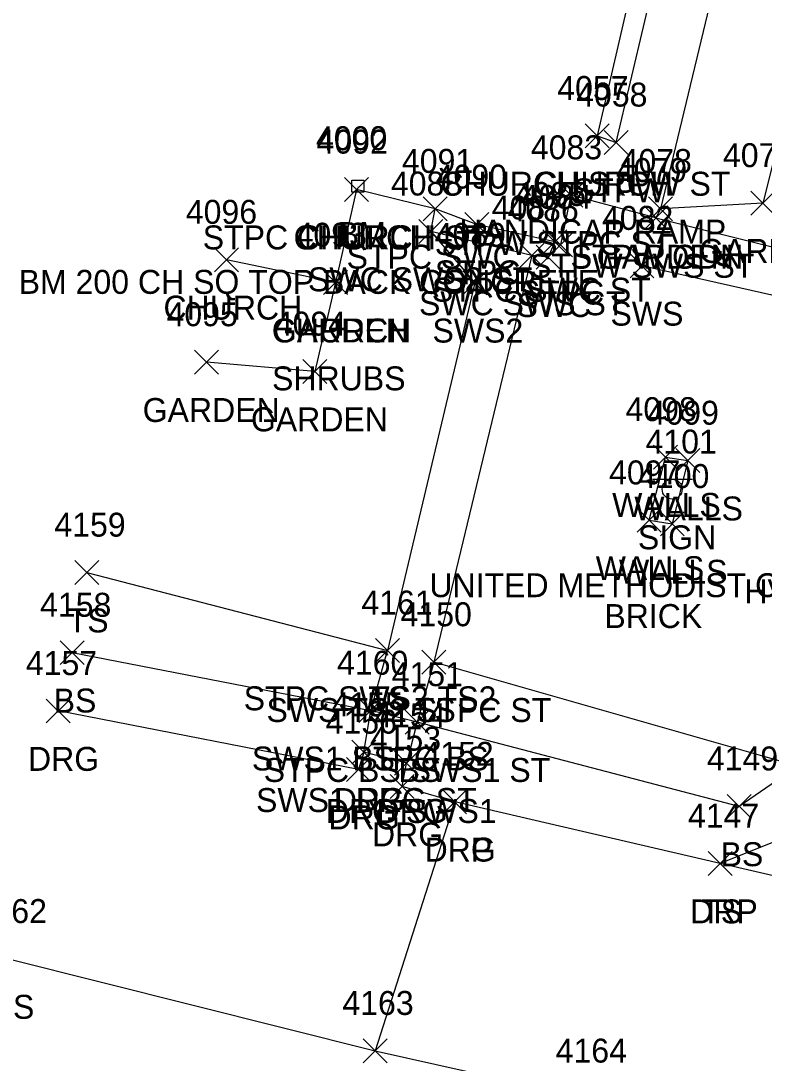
# Model space of a CAD drawing. Extents: x 1443912 to 1445411, y 621446 to 623693.
# Drawn here: x 1444916.3 to 1444978.4, y 623518.7 to 623605.8 of the extents above; entities that cross this region are included whole.
import ezdxf

# ---------------------------------------------------------------- set-up
doc = ezdxf.new("R2010")
doc.units = 0
for name, color, linetype in [('C_A', 7, 'Continuous'), ('C_C', 7, 'Continuous'), ('C_I', 7, 'Continuous'), ('CPBM', 7, 'Continuous'), ('L_A', 7, 'Continuous'), ('L_C', 7, 'Continuous'), ('L_I', 7, 'Continuous'), ('L_TIC', 7, 'Continuous'), ('LAPB', 7, 'Continuous'), ('LBC', 7, 'Continuous'), ('LBF', 7, 'Continuous'), ('LELB', 7, 'Continuous'), ('LWS', 7, 'Continuous'), ('R_A', 7, 'Continuous'), ('R_I', 7, 'Continuous'), ('R_TIC', 7, 'Continuous'), ('RDG', 7, 'Continuous'), ('RDP', 7, 'Continuous'), ('RSW', 7, 'Continuous'), ('S_A', 7, 'Continuous'), ('S_C', 7, 'Continuous'), ('S_I', 7, 'Continuous'), ('SSGN', 7, 'Continuous')]:
    doc.layers.add(name, color=color, linetype=linetype)

msp = doc.modelspace()

# ---------------------------------------------------------------- linework, layer by layer
at = {"layer": 'CPBM'}
for p, q in [((1444943.962, 623591.516), (1444943.962, 623592.516)), ((1444943.962, 623592.516), (1444944.962, 623592.516)), ((1444944.962, 623592.516), (1444944.962, 623591.516)), ((1444944.962, 623591.516), (1444943.962, 623591.516)), ((1444944.465, 623592.017), (1444944.465, 623592.017)), ((1444944.465, 623592.017), (1444944.465, 623592.017))]:
    msp.add_line(p, q, dxfattribs=at)
at = {"layer": 'L_TIC'}
for points in [[(1444963.441, 623595.216), (1444965.441, 623597.216)], [(1444965.441, 623595.216), (1444963.441, 623597.216)], [(1444963.441, 623595.216), (1444965.441, 623597.216)], [(1444965.441, 623595.216), (1444963.441, 623597.216)], [(1444965.022, 623594.665), (1444967.022, 623596.665)], [(1444967.022, 623594.665), (1444965.022, 623596.665)], [(1444943.347, 623590.734), (1444945.347, 623592.734)], [(1444945.347, 623590.734), (1444943.347, 623592.734)], [(1444943.347, 623590.734), (1444945.347, 623592.734)], [(1444945.347, 623590.734), (1444943.347, 623592.734)], [(1444961.24, 623590.26), (1444963.24, 623592.26)], [(1444963.24, 623590.26), (1444961.24, 623592.26)], [(1444961.24, 623590.26), (1444963.24, 623592.26)], [(1444963.24, 623590.26), (1444961.24, 623592.26)], [(1444977.278, 623589.604), (1444979.278, 623591.604)], [(1444979.278, 623589.604), (1444977.278, 623591.604)], [(1444949.909, 623589.126), (1444951.909, 623591.126)], [(1444951.909, 623589.126), (1444949.909, 623591.126)], [(1444968.731, 623589.117), (1444970.731, 623591.117)], [(1444970.731, 623589.117), (1444968.731, 623591.117)], [(1444968.731, 623589.117), (1444970.731, 623591.117)], [(1444970.731, 623589.117), (1444968.731, 623591.117)], [(1444953.38, 623587.81), (1444955.38, 623589.81)], [(1444955.38, 623587.81), (1444953.38, 623589.81)], [(1444968.347, 623588.362), (1444970.347, 623590.362)], [(1444970.347, 623588.362), (1444968.347, 623590.362)], [(1444959.893, 623586.361), (1444961.893, 623588.361)], [(1444961.893, 623586.361), (1444959.893, 623588.361)], [(1444960.374, 623586.124), (1444962.374, 623588.124)], [(1444962.374, 623586.124), (1444960.374, 623588.124)], [(1444932.488, 623584.869), (1444934.488, 623586.869)], [(1444934.488, 623584.869), (1444932.488, 623586.869)], [(1444941.6, 623582.957), (1444943.6, 623584.957)], [(1444943.6, 623582.957), (1444941.6, 623584.957)], [(1444941.6, 623582.957), (1444943.6, 623584.957)], [(1444943.6, 623582.957), (1444941.6, 623584.957)], [(1444930.822, 623576.314), (1444932.822, 623578.314)], [(1444932.822, 623576.314), (1444930.822, 623578.314)], [(1444939.858, 623575.53), (1444941.858, 623577.53)], [(1444941.858, 623575.53), (1444939.858, 623577.53)], [(1444969.143, 623568.383), (1444971.143, 623570.383)], [(1444971.143, 623568.383), (1444969.143, 623570.383)], [(1444970.995, 623568.087), (1444972.995, 623570.087)], [(1444972.995, 623568.087), (1444970.995, 623570.087)], [(1444967.768, 623563.099), (1444969.768, 623565.099)], [(1444969.768, 623563.099), (1444967.768, 623565.099)], [(1444967.768, 623563.099), (1444969.768, 623565.099)], [(1444969.768, 623563.099), (1444967.768, 623565.099)], [(1444969.71, 623562.797), (1444971.71, 623564.797)], [(1444971.71, 623562.797), (1444969.71, 623564.797)], [(1444969.71, 623562.797), (1444971.71, 623564.797)], [(1444971.71, 623562.797), (1444969.71, 623564.797)], [(1444920.821, 623558.733), (1444922.821, 623560.733)], [(1444922.821, 623558.733), (1444920.821, 623560.733)], [(1444919.617, 623552.041), (1444921.617, 623554.041)], [(1444921.617, 623552.041), (1444919.617, 623554.041)], [(1444945.925, 623552.226), (1444947.925, 623554.226)], [(1444947.925, 623552.226), (1444945.925, 623554.226)], [(1444945.925, 623552.226), (1444947.925, 623554.226)], [(1444947.925, 623552.226), (1444945.925, 623554.226)], [(1444949.804, 623551.247), (1444951.804, 623553.247)], [(1444951.804, 623551.247), (1444949.804, 623553.247)], [(1444949.804, 623551.247), (1444951.804, 623553.247)], [(1444951.804, 623551.247), (1444949.804, 623553.247)], [(1444944.548, 623547.198), (1444946.548, 623549.198)], [(1444946.548, 623547.198), (1444944.548, 623549.198)], [(1444944.548, 623547.198), (1444946.548, 623549.198)], [(1444946.548, 623547.198), (1444944.548, 623549.198)], [(1444948.406, 623546.241), (1444950.406, 623548.241)], [(1444950.406, 623546.241), (1444948.406, 623548.241)], [(1444948.406, 623546.241), (1444950.406, 623548.241)], [(1444950.406, 623546.241), (1444948.406, 623548.241)], [(1444975.298, 623539.202), (1444977.298, 623541.202)], [(1444977.298, 623539.202), (1444975.298, 623541.202)], [(1444973.709, 623534.424), (1444975.709, 623536.424)], [(1444975.709, 623534.424), (1444973.709, 623536.424)], [(1444944.908, 623518.775), (1444946.908, 623520.775)], [(1444946.908, 623518.775), (1444944.908, 623520.775)]]:
    msp.add_lwpolyline(points, dxfattribs=at)
at = {"layer": 'LAPB'}
for points in [[(1444978.069, 623624.879), (1444985.504, 623619.429), (1444978.278, 623590.604), (1444969.731, 623590.117)], [(1444942.6, 623583.957), (1444940.858, 623576.53), (1444931.822, 623577.314)]]:
    msp.add_lwpolyline(points, dxfattribs=at)
at = {"layer": 'LBC'}
for points in [[(1444972.255, 623630.072), (1444964.441, 623596.216)], [(1444944.347, 623591.734), (1444942.6, 623583.957), (1444933.488, 623585.869)]]:
    msp.add_lwpolyline(points, dxfattribs=at)
at = {"layer": 'LBF'}
for points in [[(1444964.441, 623596.216), (1444966.022, 623595.665), (1444973.192, 623626.107), (1444978.069, 623624.879), (1444969.731, 623590.117), (1444969.347, 623589.362), (1444962.24, 623591.26)], [(1444962.24, 623591.26), (1444961.374, 623587.124), (1444960.893, 623587.361), (1444954.38, 623588.81), (1444950.909, 623590.126), (1444944.347, 623591.734)], [(1444950.804, 623552.247), (1444949.406, 623547.241), (1444945.548, 623548.198), (1444946.925, 623553.226)]]:
    msp.add_lwpolyline(points, dxfattribs=at)
at = {"layer": 'LELB'}
for points in [[(1444990.989, 623580.204), (1444981.2, 623543.556), (1444976.298, 623540.202), (1444949.406, 623547.241)], [(1444921.821, 623559.733), (1444946.925, 623553.226)], [(1444920.617, 623553.041), (1444945.548, 623548.198)], [(1444981.2, 623543.556), (1444950.804, 623552.247)], [(1444986.637, 623540.215), (1444974.709, 623535.424)], [(1444915.29, 623527.453), (1444945.908, 623519.775)]]:
    msp.add_lwpolyline(points, dxfattribs=at)
at = {"layer": 'LWS'}
for points in [[(1444968.768, 623564.099), (1444970.143, 623569.383), (1444971.995, 623569.087), (1444970.71, 623563.797)], [(1444968.768, 623564.099), (1444970.71, 623563.797)]]:
    msp.add_lwpolyline(points, dxfattribs=at)
at = {"layer": 'R_TIC'}
for points in [[(1444949.909, 623589.126), (1444951.909, 623591.126)], [(1444951.909, 623589.126), (1444949.909, 623591.126)], [(1444968.347, 623588.362), (1444970.347, 623590.362)], [(1444970.347, 623588.362), (1444968.347, 623590.362)], [(1444949.555, 623587.232), (1444951.555, 623589.232)], [(1444951.555, 623587.232), (1444949.555, 623589.232)], [(1444949.555, 623587.232), (1444951.555, 623589.232)], [(1444951.555, 623587.232), (1444949.555, 623589.232)], [(1444959.893, 623586.361), (1444961.893, 623588.361)], [(1444961.893, 623586.361), (1444959.893, 623588.361)], [(1444957.972, 623585.229), (1444959.972, 623587.229)], [(1444959.972, 623585.229), (1444957.972, 623587.229)], [(1444957.972, 623585.229), (1444959.972, 623587.229)], [(1444959.972, 623585.229), (1444957.972, 623587.229)], [(1444959.339, 623585.082), (1444961.339, 623587.082)], [(1444961.339, 623585.082), (1444959.339, 623587.082)], [(1444967.178, 623584.362), (1444969.178, 623586.362)], [(1444969.178, 623584.362), (1444967.178, 623586.362)], [(1444953.216, 623582.948), (1444955.216, 623584.948)], [(1444955.216, 623582.948), (1444953.216, 623584.948)], [(1444945.925, 623552.226), (1444947.925, 623554.226)], [(1444947.925, 623552.226), (1444945.925, 623554.226)], [(1444949.804, 623551.247), (1444951.804, 623553.247)], [(1444951.804, 623551.247), (1444949.804, 623553.247)], [(1444918.431, 623547.167), (1444920.431, 623549.167)], [(1444920.431, 623547.167), (1444918.431, 623549.167)], [(1444944.548, 623547.198), (1444946.548, 623549.198)], [(1444946.548, 623547.198), (1444944.548, 623549.198)], [(1444948.406, 623546.241), (1444950.406, 623548.241)], [(1444950.406, 623546.241), (1444948.406, 623548.241)], [(1444943.956, 623543.728), (1444945.956, 623545.728)], [(1444945.956, 623543.728), (1444943.956, 623545.728)], [(1444943.956, 623543.728), (1444945.956, 623545.728)], [(1444945.956, 623543.728), (1444943.956, 623545.728)], [(1444947.522, 623542.813), (1444949.522, 623544.813)], [(1444949.522, 623542.813), (1444947.522, 623544.813)], [(1444947.522, 623542.813), (1444949.522, 623544.813)], [(1444949.522, 623542.813), (1444947.522, 623544.813)], [(1444943.516, 623542.275), (1444945.516, 623544.275)], [(1444945.516, 623542.275), (1444943.516, 623544.275)], [(1444947.148, 623540.856), (1444949.148, 623542.856)], [(1444949.148, 623540.856), (1444947.148, 623542.856)], [(1444951.54, 623539.586), (1444953.54, 623541.586)], [(1444953.54, 623539.586), (1444951.54, 623541.586)], [(1444951.54, 623539.586), (1444953.54, 623541.586)], [(1444953.54, 623539.586), (1444951.54, 623541.586)], [(1444973.709, 623534.424), (1444975.709, 623536.424)], [(1444975.709, 623534.424), (1444973.709, 623536.424)], [(1444944.908, 623518.775), (1444946.908, 623520.775)], [(1444946.908, 623518.775), (1444944.908, 623520.775)]]:
    msp.add_lwpolyline(points, dxfattribs=at)
at = {"layer": 'RDG'}
for points in [[(1444944.956, 623544.728), (1444944.516, 623543.275), (1444919.431, 623548.167)], [(1444952.54, 623540.586), (1444948.148, 623541.856), (1444948.522, 623543.813)]]:
    msp.add_lwpolyline(points, dxfattribs=at)
at = {"layer": 'RDP'}
msp.add_lwpolyline([(1444989.647, 623532.72), (1444984.082, 623533.247), (1444974.709, 623535.424), (1444952.54, 623540.586), (1444945.908, 623519.775), (1444963.712, 623515.793), (1444978.902, 623513.727), (1444983.263, 623509.219)], dxfattribs=at)
at = {"layer": 'RSW'}
for points in [[(1444960.893, 623587.361), (1444960.339, 623586.082), (1444958.972, 623586.229), (1444950.555, 623588.232), (1444950.909, 623590.126)], [(1444969.347, 623589.362), (1444991.751, 623583.781), (1444990.989, 623580.204), (1444968.178, 623585.362)], [(1444950.555, 623588.232), (1444954.216, 623583.948), (1444946.925, 623553.226)], [(1444958.972, 623586.229), (1444950.804, 623552.247)], [(1444949.406, 623547.241), (1444948.522, 623543.813), (1444944.956, 623544.728), (1444945.548, 623548.198)]]:
    msp.add_lwpolyline(points, dxfattribs=at)
at = {"layer": 'SSGN'}
for p, q in [((1444969.053, 623567.531), (1444972.386, 623567.531)), ((1444970.699, 623566.698), (1444970.699, 623566.698))]:
    msp.add_line(p, q, dxfattribs=at)
msp.add_circle((1444970.699, 623566.698), 0.833, dxfattribs=at)

# ---------------------------------------------------------------- texts
at = {"layer": 'C_A'}
for s, p in [('BM', (1444942.78, 623587.017)), ('HVCTRL', (1444976.73, 623557.157))]:
    msp.add_text(s, height=2, dxfattribs=at).set_placement(p)
at = {"layer": 'C_C'}
msp.add_text('BM 200 CH SQ TOP BACK CONCRETE', height=2, dxfattribs=at).set_placement((1444916.135, 623583.017))
at = {"layer": 'C_I'}
msp.add_text('4000', height=2, dxfattribs=at).set_placement((1444940.961, 623595.017))
at = {"layer": 'L_A'}
for s, p in [('CHURCH STPW ST', (1444951.347, 623591.216)), ('CHURCH', (1444959.181, 623591.216)), ('STPW', (1444962.415, 623590.665)), ('STPC CHURCH ST', (1444931.505, 623586.734)), ('CHURCH', (1444939.088, 623586.734)), ('STPW STPC ST', (1444950.878, 623586.26)), ('STPW STPC ST', (1444950.878, 623586.26)), ('STPC SWC', (1444943.516, 623585.126)), ('STPW GDN', (1444962.212, 623585.117)), ('GARDEN', (1444964.401, 623585.117)), ('GARDEN', (1444972.947, 623585.604)), ('STPW SWS ST', (1444958.835, 623584.362)), ('STPC', (1444950.892, 623583.81)), ('STPC SWC ST', (1444950.633, 623582.361)), ('STPC', (1444957.886, 623582.124)), ('CHURCH', (1444928.228, 623580.869)), ('GARDEN', (1444937.27, 623578.957)), ('CHURCH', (1444937.341, 623578.957)), ('GARDEN', (1444926.491, 623572.314)), ('GARDEN', (1444935.528, 623571.53)), ('WALLS', (1444965.686, 623564.383)), ('WALLS', (1444967.539, 623564.087)), ('WALLS', (1444964.312, 623559.099)), ('WALLS', (1444964.312, 623559.099)), ('WALLS', (1444966.253, 623558.797)), ('WALLS', (1444966.253, 623558.797)), ('TS', (1444920.231, 623554.733)), ('BS', (1444919.058, 623548.041)), ('STPC SWS2 TS2', (1444934.925, 623548.226)), ('TS', (1444945.334, 623548.226)), ('SWS TS2 STPC ST', (1444936.828, 623547.247)), ('TS', (1444949.214, 623547.247)), ('SWS1 STPC BS', (1444935.612, 623543.198)), ('BS', (1444943.989, 623543.198)), ('STPC BS SWS1 ST', (1444936.595, 623542.241)), ('BS', (1444947.847, 623542.241)), ('BS', (1444974.739, 623535.202)), ('TS', (1444973.119, 623530.424)), ('CS', (1444913.731, 623522.453))]:
    msp.add_text(s, height=2, dxfattribs=at).set_placement(p)
at = {"layer": 'L_C'}
for s, p in [('HANDICAP RAMP', (1444952.922, 623587.216)), ('SHRUBS', (1444937.293, 623574.957)), ('BRICK', (1444965.036, 623555.099)), ('BRICK', (1444965.036, 623555.099))]:
    msp.add_text(s, height=2, dxfattribs=at).set_placement(p)
at = {"layer": 'L_I'}
for s, p in [('4057', (1444961.103, 623599.216)), ('4057', (1444961.103, 623599.216)), ('4058', (1444962.683, 623598.665)), ('4092', (1444941.009, 623594.734)), ('4092', (1444941.009, 623594.734)), ('4083', (1444958.901, 623594.26)), ('4083', (1444958.901, 623594.26)), ('4091', (1444948.138, 623593.126)), ('4078', (1444966.393, 623593.117)), ('4078', (1444966.393, 623593.117)), ('4077', (1444974.939, 623593.604)), ('4079', (1444966.001, 623592.362)), ('4090', (1444950.955, 623591.81)), ('4085', (1444957.554, 623590.361)), ('4084', (1444958.035, 623590.124)), ('4096', (1444930.094, 623588.869)), ('4093', (1444939.262, 623586.957)), ('4093', (1444939.262, 623586.957)), ('4095', (1444928.483, 623580.314)), ('4094', (1444937.52, 623579.53)), ('4098', (1444966.804, 623572.383)), ('4099', (1444968.649, 623572.087)), ('4097', (1444965.43, 623567.099)), ('4097', (1444965.43, 623567.099)), ('4100', (1444967.852, 623566.797)), ('4100', (1444967.852, 623566.797)), ('4159', (1444919.121, 623562.733)), ('4158', (1444917.924, 623556.041)), ('4161', (1444944.752, 623556.226)), ('4161', (1444944.752, 623556.226)), ('4150', (1444948.025, 623555.247)), ('4150', (1444948.025, 623555.247)), ('4160', (1444942.722, 623551.198)), ('4160', (1444942.722, 623551.198)), ('4151', (1444947.28, 623550.241)), ('4151', (1444947.28, 623550.241)), ('4149', (1444973.597, 623543.202)), ('4147', (1444972.017, 623538.424)), ('4162', (1444912.55, 623530.453)), ('4163', (1444943.168, 623522.775))]:
    msp.add_text(s, height=2, dxfattribs=at).set_placement(p)
at = {"layer": 'R_A'}
for s, p in [('STPC SWC', (1444943.516, 623585.126)), ('STPW SWS ST', (1444958.835, 623584.362)), ('SWC SWS2 ST', (1444940.295, 623583.232)), ('SWC SWS2 ST', (1444940.295, 623583.232)), ('STPC SWC ST', (1444950.633, 623582.361)), ('SWC SWS ST', (1444949.562, 623581.229)), ('SWC SWS ST', (1444949.562, 623581.229)), ('SWC', (1444957.701, 623581.082)), ('SWS', (1444965.548, 623580.362)), ('SWS2', (1444950.688, 623578.948)), ('STPC SWS2 TS2', (1444934.925, 623548.226)), ('SWS TS2 STPC ST', (1444936.828, 623547.247)), ('DRG', (1444916.919, 623543.167)), ('SWS1 STPC BS', (1444935.612, 623543.198)), ('STPC BS SWS1 ST', (1444936.595, 623542.241)), ('SWS1 DRG ST', (1444935.956, 623539.728)), ('DRG', (1444942.444, 623539.728)), ('DRG SWS1', (1444941.781, 623538.813)), ('DRG', (1444942.005, 623538.275)), ('DRG', (1444946.01, 623538.813)), ('DRG', (1444945.636, 623536.856)), ('DRG', (1444950.028, 623535.586)), ('DRP', (1444950.028, 623535.586)), ('DRP', (1444972.198, 623530.424))]:
    msp.add_text(s, height=2, dxfattribs=at).set_placement(p)
at = {"layer": 'R_I'}
for s, p in [('4091', (1444948.138, 623593.126)), ('4079', (1444966.001, 623592.362)), ('4088', (1444947.216, 623591.232)), ('4088', (1444947.216, 623591.232)), ('4085', (1444957.554, 623590.361)), ('4087', (1444955.633, 623589.229)), ('4087', (1444955.633, 623589.229)), ('4086', (1444956.945, 623589.082)), ('4082', (1444964.839, 623588.362)), ('4089', (1444950.87, 623586.948)), ('4161', (1444944.752, 623556.226)), ('4150', (1444948.025, 623555.247)), ('4157', (1444916.738, 623551.167)), ('4160', (1444942.722, 623551.198)), ('4151', (1444947.28, 623550.241)), ('4155', (1444942.263, 623547.728)), ('4155', (1444942.263, 623547.728)), ('4154', (1444945.829, 623546.813)), ('4154', (1444945.829, 623546.813)), ('4156', (1444941.769, 623546.275)), ('4153', (1444945.455, 623544.856)), ('4152', (1444949.847, 623543.586)), ('4152', (1444949.847, 623543.586)), ('4147', (1444972.017, 623538.424)), ('4163', (1444943.168, 623522.775)), ('4164', (1444960.972, 623518.793)), ('4164', (1444960.972, 623518.793))]:
    msp.add_text(s, height=2, dxfattribs=at).set_placement(p)
at = {"layer": 'S_A'}
msp.add_text('SIGN', height=2, dxfattribs=at).set_placement((1444967.837, 623561.677))
at = {"layer": 'S_C'}
msp.add_text('UNITED METHODIST CHURCH', height=2, dxfattribs=at).set_placement((1444950.428, 623557.677))
at = {"layer": 'S_I'}
msp.add_text('4101', height=2, dxfattribs=at).set_placement((1444968.475, 623569.677))

doc.saveas('drawing.dxf')
